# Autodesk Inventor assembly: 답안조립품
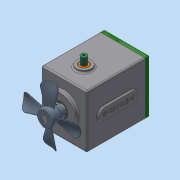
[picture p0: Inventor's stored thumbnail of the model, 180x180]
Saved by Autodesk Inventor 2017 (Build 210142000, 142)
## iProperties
Part Number: 답안조립품
Material: 일반
Document SubType Name: Assembly
Designer: MRC
Author: MRC
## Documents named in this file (17)
- C:\Users\MRC\Desktop\610205V1006\답안조립품.iam
- C:\Users\MRC\Desktop\610205V1006\본체.ipt
- C:\Users\MRC\Desktop\610205V1006\가변스프링.ipt
- C:\Users\MRC\Desktop\610205V1006\멈춤나사 M3x8.ipt
- C:\Users\MRC\Desktop\610205V1006\메인 기어 축.ipt
- C:\Users\MRC\Desktop\610205V1006\베어링 608.ipt
- C:\Users\MRC\Desktop\610205V1006\베어링 6903.ipt
- C:\Users\MRC\Desktop\610205V1006\볼트 M4 x 10.ipt
- C:\Users\MRC\Desktop\610205V1006\부시.ipt
- C:\Users\MRC\Desktop\610205V1006\서브 기어 축.ipt
- C:\Users\MRC\Desktop\610205V1006\슬라이더.ipt
- C:\Users\MRC\Desktop\610205V1006\오일 실 8 22 7.ipt
- C:\Users\MRC\Desktop\610205V1006\오일 실 17 30 8.ipt
- C:\Users\MRC\Desktop\610205V1006\커버.ipt
- C:\Users\MRC\Desktop\610205V1006\키 5 x 5 x 24.ipt
- C:\Users\MRC\Desktop\610205V1006\팬날개.ipt
- 팬날개.ipt
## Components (1 placed, 1 different names)
1. 가변스프링:1
